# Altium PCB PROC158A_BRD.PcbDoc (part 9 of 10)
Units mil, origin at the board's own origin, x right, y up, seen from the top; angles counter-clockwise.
Board outline 3346.45 x 4921.26 mil, 8 copper layers (Top Layer, GND1, SIG1, PWR1, PWR2, SIG2, GND2, Bottom Layer), stack 54.534 mil thick; 718 components, 459 nets, 2307 pads, 1179 vias.
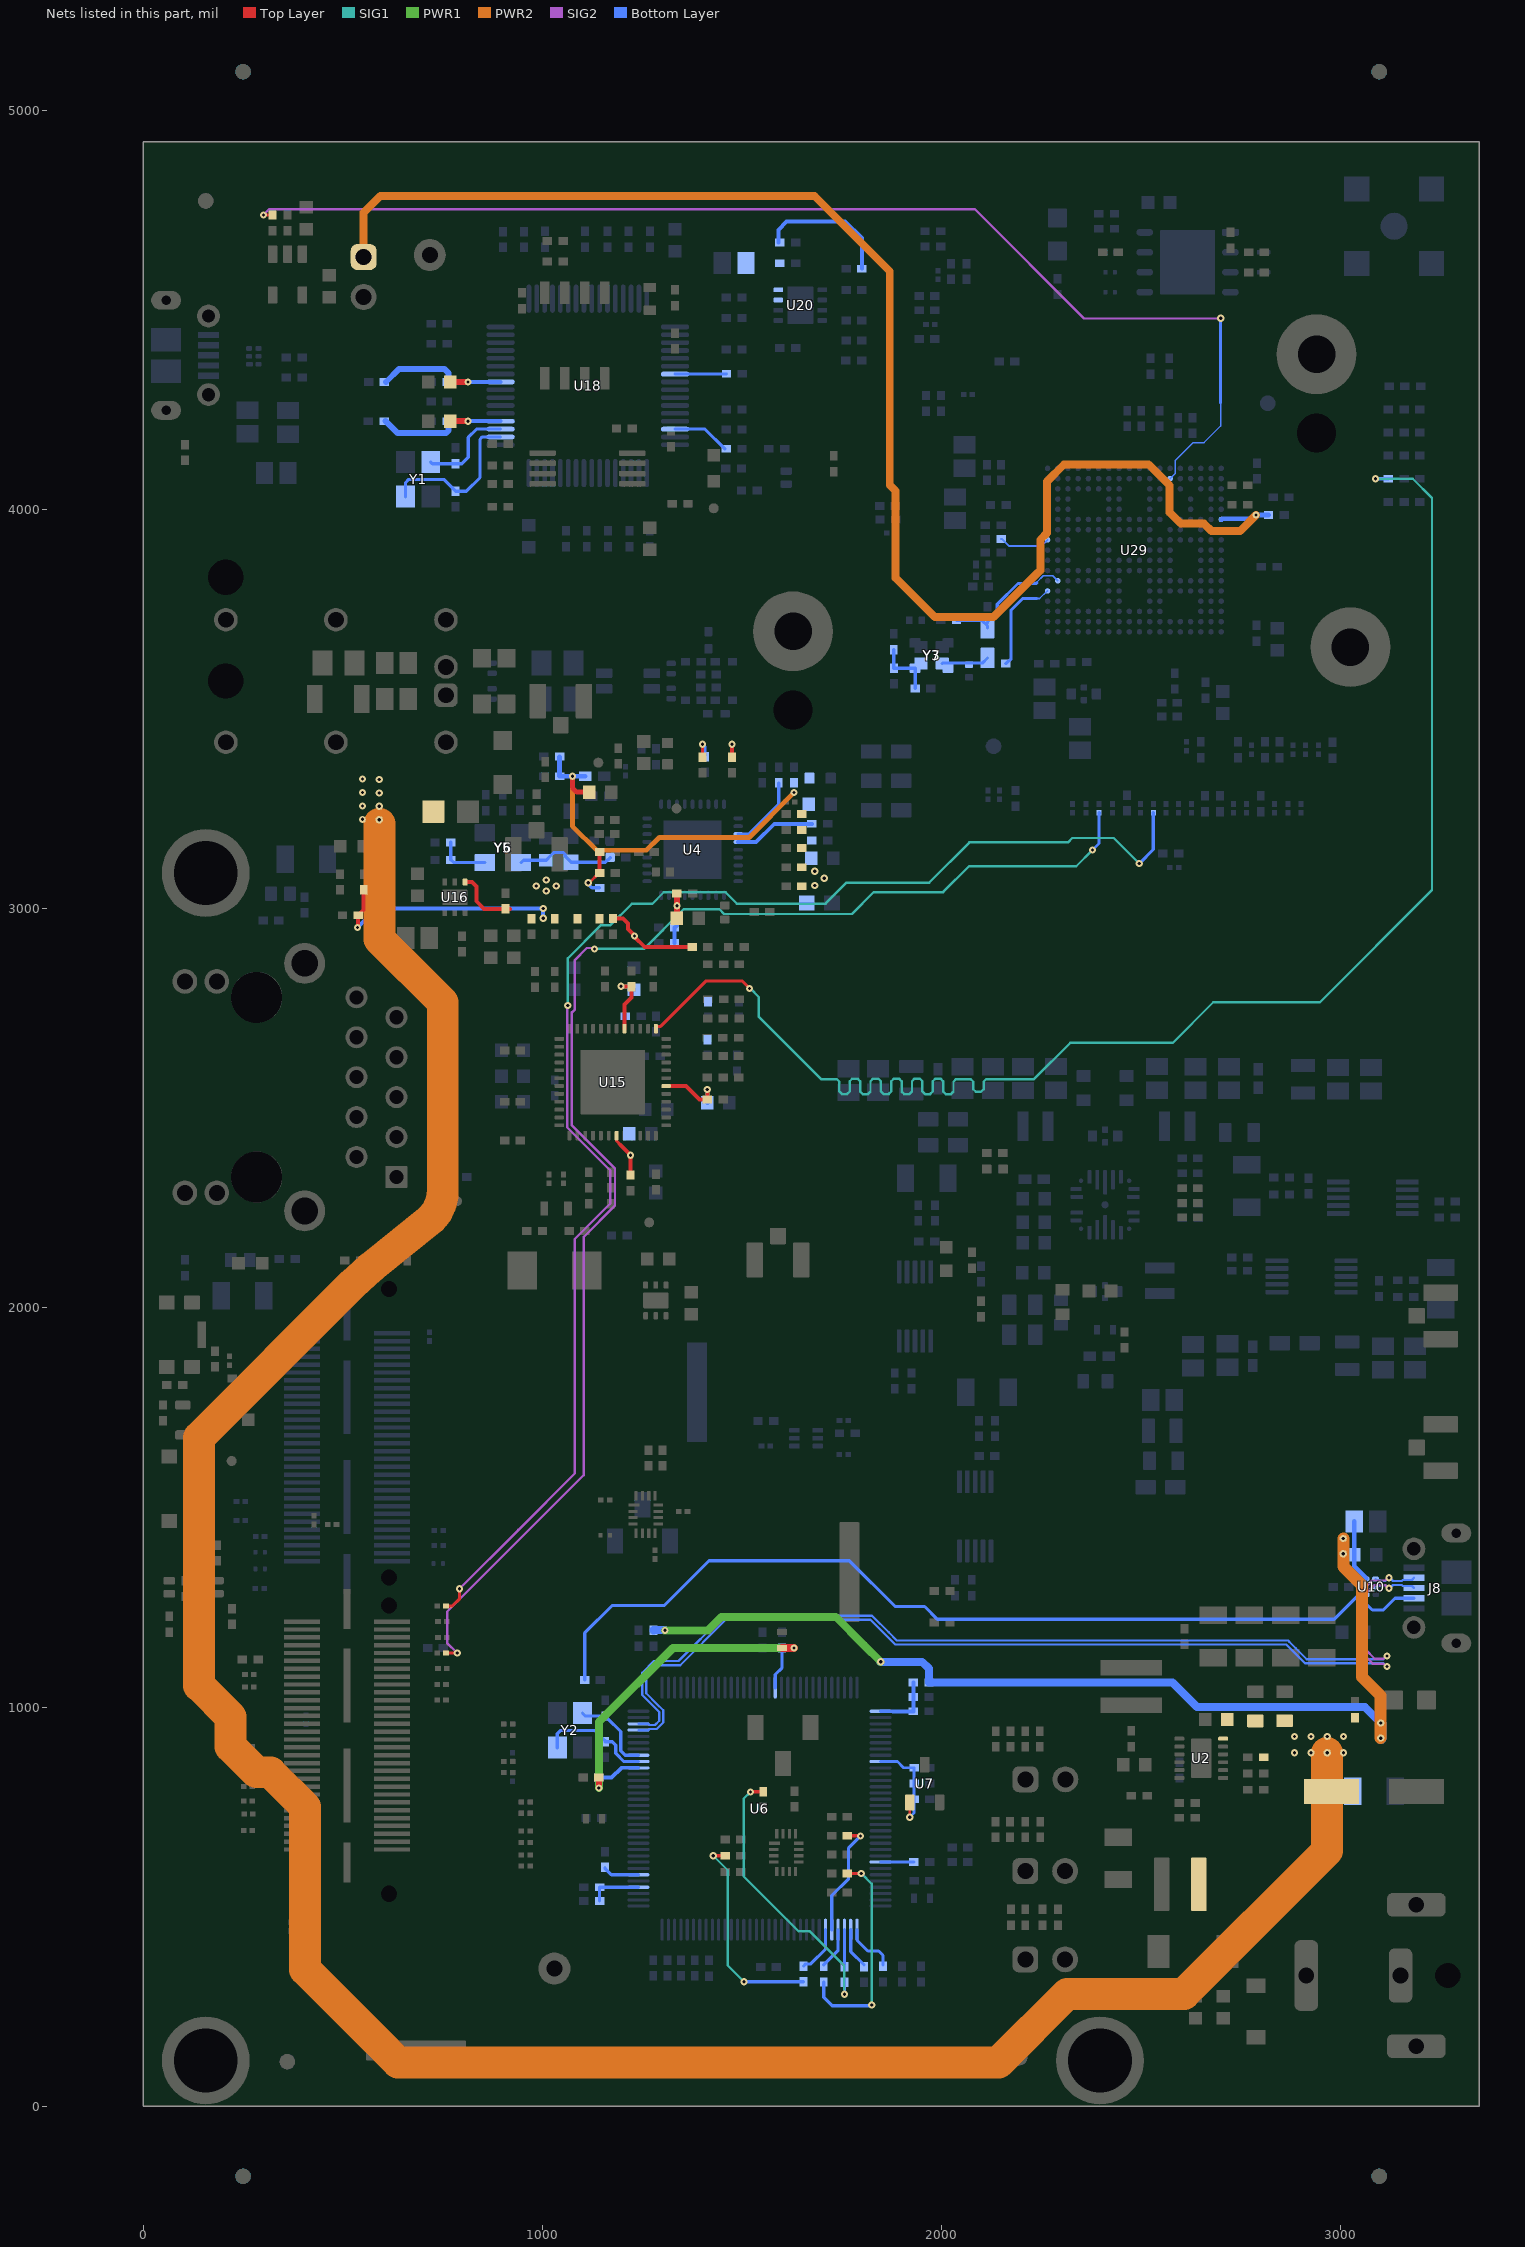
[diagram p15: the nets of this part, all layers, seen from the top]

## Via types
v1: diameter 18, hole 8, Top Layer to Bottom Layer, tented both sides, 1112 vias
v2: diameter 19.68, hole 7.87, Top Layer to Bottom Layer, 28 vias
v3: diameter 20, hole 10, Top Layer to Bottom Layer, tented both sides, 26 vias
v4: diameter 16/18/18/18/18/18/18/16 (per signal layer), hole 8, Top Layer to Bottom Layer, tented both sides, 13 vias

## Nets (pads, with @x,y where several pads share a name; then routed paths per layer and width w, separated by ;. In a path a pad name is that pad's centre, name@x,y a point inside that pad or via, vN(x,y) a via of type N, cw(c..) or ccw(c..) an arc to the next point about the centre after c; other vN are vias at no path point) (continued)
TX_CTRL: R101.2 U15.37 | length 3914.5
  Top Layer w8: U15.37@1284.77,2705.1 1295.97,2705.1 1410.08,2819.22 1499.78,2819.22 v1(1519,2800)
  SIG1 w6: v1(1519,2800) 1520.85,2800 1542,2778.85 1542,2773.48 1542.06,2773.42 1542.06,2728.92 1698.02,2572.95 1708.25,2572.95 1737.25,2572.95 1743.75,2566.45 1743.75,2542 1750.25,2535.5 1763.25,2535.5 1769.75,2542 1769.75,2567.88 1776.25,2574.38 1789.25,2574.38 1795.75,2567.88 1795.75,2542 1802.25,2535.5 1815.25,2535.5 1821.75,2542 1821.75,2567.88 1828.25,2574.38 1841.25,2574.38 1847.75,2567.88 1847.75,2542 1854.25,2535.5 1867.25,2535.5 1873.75,2542 1873.75,2567.88 1880.25,2574.38 1893.25,2574.38 1899.75,2567.88 1899.75,2542 1906.25,2535.5 1919.25,2535.5 1925.75,2542 1925.75,2567.88 1932.25,2574.38 1945.25,2574.38 1951.75,2567.88 1951.75,2542 1958.25,2535.5 1971.25,2535.5 1977.75,2542 1977.75,2567.88 1984.25,2574.38 1997.25,2574.38 2003.75,2567.88 2003.75,2542 2010.25,2535.5 2023.25,2535.5 2029.75,2542 2029.75,2566.45 2036.25,2572.95 2043.33,2572.95 2043.7,2572.95 2072.7,2572.95 2079.2,2566.45 2079.2,2547.8 2085.7,2541.3 2098.7,2541.3 2105.2,2547.8 2105.2,2566.45 2111.7,2572.95 2123.07,2572.95 2231.45,2572.95 2322.24,2663.74 2578.84,2663.74 2680.58,2765.48 2947.48,2765.48 3228.45,3046.45 3228.45,4028.55 3180.03,4076.97 v1(3087,4076.97)
  Bottom Layer w8: v1(3087,4076.97) R101.2@3119.26,4076.97
UART_TX_FTDI: R131.2 U18.39 | length 129.2
  Bottom Layer w8: U18.39@1332.18,4339.21 1332.55,4339.59 1460.69,4339.59 R131.2@1461.03,4339.25
V_GND: C172.2 R76.2 R79.2 Y5.4 Y6.4 | length 132.7
  Bottom Layer w8: R76.2@770.13,3166.22 R79.2@770.13,3121.72 772.1,3121.72 778.38,3115.44 Y5.4@855.78,3115.44
V_GND_50MHz: C178.2 R86.2 R87.2 Y3.4 Y7.4 | length 151.6
  Bottom Layer w8: R87.2@1879.89,3648.94 1879.89,3601.94 C178.2@1880.27,3602.32 1933.16,3602.32 Y7.4@1933.55,3602.71 ; R86.2@1933.67,3551.94 Y3.4@1933.67,3602.59
VBAT_INT: C99.1 C101.1 C118.2 C173.2 C195.1 L5.2 R7.1 R191.2 R331.2 U2.12 | length 6447.8
  PWR2 w80: 592.01,3212.8 592.01,2923.53 750.25,2765.29 750.25,2293.1 cw(c650.25,2293.1) 720.96,2222.39 571.45,2101.97 ccw(c615.41,2047.39) 568.51,2099.47 524.32,2059.68 140,1675.35 140,1054.38 219,975.38 219,901.22 283.46,836.75 318.21,836.75 405,749.97 405,343 638.59,109.41 2142.58,109.41 2314.68,281.5 2607.23,281.5 2965.84,640.11 v1(2965.84,885.39)
  other v1: 2884,885.39 2924.92,885.39 3006.76,885.39 2884,926.31 2924.92,926.31 2965.84,926.31 3006.76,926.31 591,3222.81 549,3223.81 591,3256.48 549,3257.48 591,3290.14 549,3291.14 591,3323.81 549,3324.81
VBGAP: C180.1 U29.K1 | length 129.9
  Bottom Layer w4.5: 2238.73,3908.81 2250.26,3908.81 2264.73,3923.28 U29.K1@2265.3,3923.84
  Bottom Layer w5: C180.1@2148.95,3926.41 2150.92,3926.41 2168.52,3908.81 2238.73,3908.81
VBUS_1_DETECT: C109.2 R284.1 R285.2 U6.1 | length 161.5
  Bottom Layer w8: U6.1@1846.93,989.49 1885.44,989.49
  Bottom Layer w10: 1878.33,989.49 R285.2@1928.95,989.49 C109.2@1928.95,1025.56 R284.1@1928.95,1061.91
VDD_1P0: C8.2 C11.2 C12.2 C13.2 C16.1 C20.1 FB2.2 R63.1 U4.21 | length 1139.3
  Top Layer w12: v1(1075.19,3331.81) 1075.19,3302.81 1086,3292 C11.2@1117,3292
  PWR2 w12: v1(1075.19,3331.81) 1075.19,3206.81 1135.75,3146.25 1260.44,3146.25 1292.5,3178.31 1517.5,3178.31 v1(1630,3290.81)
  Bottom Layer w8: U4.21@1490.4,3186.96 1517.06,3186.96 1592,3261.9 C20.1@1592,3315.13
  Bottom Layer w12: C12.2@1043,3380.81 C16.1@1043,3331.81 v1(1075.19,3331.81) R63.1@1107.38,3331.81
VDDC_1: C62.1 C64.2 C74.2 C75.2 U6.87 U6.115 | length 1055.2
  Top Layer w15: v1(1141.26,797.62) C74.2@1141.26,823.24
  Top Layer w20: C62.1@1600.04,1147.93 v1(1630,1147.93)
  PWR1 w20: v1(1141.26,797.62) 1141.26,962.26 1326.93,1147.93 v1(1630,1147.93)
  Bottom Layer w8: 1197.58,847.76 U6.87@1240.63,847.76 ; U6.115@1583.15,1048.54 1583.15,1081.5 1600.44,1098.79 C64.2@1600.44,1147.93 v1(1630,1147.93)
  Bottom Layer w10: v1(1141.26,797.62) C75.2@1141.26,823.24 ; C75.2@1143.21,823.24 1173.07,823.24 1197.58,847.76
VDDIO_ETH: C53.1 C158.1 C183.1 C184.1 C185.1 C186.1 R92.2 R108.2 R112.2 R132.2 R139.2 R141.2 R173.2 R211.2 R286.2 R295.1 R340.2 R342.2 U15.19 U15.30 U15.41 U16.4 | length 1471.7
  Top Layer w8: U15.19@1185.77,2431.68 1185.77,2418 1195.97,2407.8
  Top Layer w10: v1(537.01,2952.49) 537.7,2953.18 537.7,2982.91 R112.2@538.39,2983.6 552.17,2997.37 R108.2@552.17,3047.15 ; U16.4@806.17,3066.73 823.15,3066.73 834.77,3055.11 834.77,3018.63 854.06,2999.34 R295.1@907.18,2999.34 918.99,2999.34 ; R141.2@1177,2975.5 1201.84,2975.5 1214.12,2963.22 1214.12,2949.03 1230.42,2932.73 v1(1230.42,2931.38) 1230.42,2929.64 1256.24,2903.81 R211.2@1374.95,2903.81 ; 1195.97,2407.8 1220.92,2382.85 v1(1220.92,2382.45) ; v1(1196.68,2805.62) 1197.25,2805.04 1222.58,2805.04 C185.1@1223.16,2804.47 1223.16,2777.86 1205.44,2760.14 1205.44,2723.38 ; U15.41@1205.46,2699.4 1205.46,2723.37 ; C184.1@1220.92,2332.83 v1@1220.92,2378.09 ; U15.30@1309.79,2555.7 1359.88,2555.7 1393.53,2522.05 1413.27,2522.05 1413.31,2522.09 1413.31,2546.79 v1@1413.63,2547.1
  Bottom Layer w10: v1(537.01,2952.49) 584.81,3000.29 v1(1001.9,3000.29) 1001.95,3000.23 1001.95,2981.11 999,2978.16 v1@999,2976 ; v1(1196.68,2805.62) 1219.66,2805.62 C53.1@1228.92,2796.36 ; C186.1@1413.03,2513.53 v1(1413.03,2547.1)
  other v1: 1001.9,2976
VDDIO_ETH2: C32.2 C35.2 C36.2 C37.1 C44.1 C46.2 FB1.2 R13.2 R15.2 R16.2 R34.1 R46.1 R252.2 R253.2 R254.2 R255.2 R256.2 R257.2 R258.2 U4.22 U4.34 | length 603.8
  Top Layer w8: v1(1114.51,3064.96) 1116.36,3066.81 1119.05,3066.81 1141.23,3088.99 R46.1@1143.2,3088.99 ; R252.2@1401.29,3383.67 v1(1401.29,3412.15)
  Top Layer w10: R46.1@1143.2,3088.99 R13.2@1143.2,3142.2 ; R254.2@1474.75,3383.67 v1(1474.75,3412.15)
  Top Layer w15: C32.2@1336.83,2976.15 v1(1336.83,3007.39) R15.2@1336.83,3038.39
  Bottom Layer w8: v1(1114.51,3064.96) 1116.42,3063.04 1116.42,3059.6 1123.81,3052.21 R34.1@1143.2,3052.21 ; v1(1401.29,3412.15) 1407.02,3406.42 R253.2@1407.02,3383.59
  Bottom Layer w10: C46.2@1330.71,2914.18 C37.1@1330.71,2952.76 1331.99,2952.76 1336.83,2957.6 v1(1336.83,3007.39) U4.34@1336.83,3033.39 ; U4.22@1490.38,3167.25 1535.44,3167.25 1580.94,3212.75 C44.1@1674.81,3212.75
  other v1: 1009.58,3044.5 984.69,3056.5 1034.63,3056.5 1682,3057.81 1009.58,3071.56 1706,3076.33 1682,3093.55
VLDO_3V3: C93.1 C94.1 R182.1 R202.2 U20.3 U20.4 | length 343.4
  Bottom Layer w10: C94.1@1590.78,4668.86 1590.78,4700.64 1611.51,4721.37 1758.38,4721.37 1800.03,4679.72 R202.2@1800.03,4603.23
VPHY_FTDI: C68.1 C69.2 L3.2 U18.4 | length 366.6
  Top Layer w15: C68.1@772.94,4221.1 v1(813.55,4221.1)
  Bottom Layer w10: v1(813.55,4221.1) U18.4@895.17,4221.1
  Bottom Layer w15: L3.2@607.41,4221.1 637.27,4191.24 758.26,4191.24 765.07,4198.05 765.07,4221.1 v1(813.55,4221.1)
VPLL_FTDI: C72.1 C73.2 L4.2 U18.9 | length 371.7
  Top Layer w15: C72.1@769,4319.53 v1(813.55,4319.53)
  Bottom Layer w10: v1(813.55,4319.53) U18.9@895.17,4319.53
  Bottom Layer w15: L4.2@608.16,4319.53 641.1,4352.47 754,4352.47 765.07,4341.41 765.07,4319.53 v1(813.55,4319.53)
VPP_1P7: C150.2 P1.1 U29.M18 | length 3770.2
  PWR2 w20: P1.1@552.17,4632.33 552.17,4743.98 594,4785.81 1681,4785.81 1870,4596.81 1870,4061.55 1885,4046.55 1885,3828.39 1982.81,3730.57 2130.21,3730.57 2239.05,3839.42 2247.12,3847.49 2247.12,3924.12 2264,3941 2264,4070 2307.11,4113.11 2518.49,4113.11 2571,4060.6 2571,3993.02 2599.5,3964.52 2657.19,3964.52 2675.8,3945.91 2747.82,3945.91 v1(2787.81,3985.9)
  Bottom Layer w12: U29.M18@2700.34,3975.02 2700.81,3975.02 2702.46,3976.68 2777.78,3976.68 2787.01,3985.9 v1(2787.81,3985.9) ; v1@2788.12,3986.2 2816.59,3986.2 2816.89,3986.51 C150.2@2818.86,3986.51
VPP_EN: R159.1 U29.T13 | length 3010
  Top Layer w8: v1(301.31,4738.05) 301.48,4737.87 323.78,4737.87 R159.1@323.96,4737.7
  SIG2 w6: v1(301.31,4738.05) 315.2,4751.94 2083.37,4751.94 2356.9,4478.41 2698.58,4478.41 v1(2699.21,4479.03)
  Bottom Layer w4: U29.T13@2572.39,4077.38 2585.22,4090.21 2585.22,4122.59 2596.81,4134.18 2597.1,4134.47 2630.3,4167.67 2657.24,4167.67 2698.74,4209.17 2698.74,4267
  Bottom Layer w8: 2698.74,4267 2698.74,4478.57 v1(2699.21,4479.03)
WRMRST_FTDI: R330.1 U18.46 | length 144.7
  Bottom Layer w8: U18.46@1332.18,4201.42 1407.28,4201.42 R330.1@1456.51,4152.19
XDS_TCK: R353.1 R387.1 | length 696.9
  Top Layer w8: v1(1521.05,787.51) 1521.24,787.7 1553.03,787.7 R353.1@1553.23,787.9
  SIG1 w6: v1(1521.05,787.51) 1503.94,770.4 1503.94,576.06 1642.02,437.98 1669.94,437.98 1756.38,351.55 v1(1756.38,280.81)
  Bottom Layer w8: v1(1756.38,280.81) R387.1@1756.38,310.62
XDS_TDI: R355.1 R389.1 | length 526
  Top Layer w8: v1(1428,627.37) R355.1@1457.48,627.37
  SIG1 w6: v1(1428,627.37) 1464,591.37 1464,352.81 v1(1505,311.81)
  Bottom Layer w8: v1(1505,311.81) R389.1@1654.05,311.78
XDS_TDO: R359.1 U6.37 | length 297.3
  Top Layer w8: R359.1@1763.89,677.81 v1@1796.39,677.81
  Bottom Layer w8: U6.37@1724.88,442.24 1724.88,527.89 1767,570 1767,647.08 v1(1797.06,677.14)
XDS_TMS: R357.1 R388.1 | length 543.3
  Top Layer w8: R357.1@1763.89,582.99 1764.08,583.17 1798.63,583.17 v1(1798.82,583.36)
  SIG1 w6: v1(1798.82,583.36) 1825,557.17 v1(1825,253.81)
  Bottom Layer w8: R388.1@1704.82,311.19 1704.82,273.11 1725.95,251.97 1823.16,251.97 v1(1825,253.81)
XDSET_1_D_N: J8.2 U6.93 U10.1 | length 2592.4
  SIG2 w5.8: v1(3115.78,1101.9) 3113.28,1101.9 3106.28,1108.9 3079.99,1108.9 3051,1137.89 3051,1289.81 3078.03,1316.84 3111.5,1316.84 3118.5,1323.84 v1(3121,1323.84)
  Bottom Layer w5.65: U6.93@1240.63,942.24 1264.86,942.24 1267.63,945.02 1286.34,945.02 1302.52,961.19 1302.52,991.91 1287.21,1007.21 1260,1034.42 1260,1081.68 1283.36,1105.04 1345.04,1105.04 1458.5,1218.5 1821.5,1218.5 1883.52,1156.48 2863.52,1156.48 2910.2,1109.8 3106.29,1109.8 3114.19,1101.9 v1(3115.78,1101.9) ; U10.1@3086.64,1320.68 3089.03,1318.3 3096.67,1318.3 3099.03,1315.94 3111.52,1315.94 3119.42,1323.84 v1(3121,1323.84) 3122.59,1323.84 3130.49,1315.94 3152.67,1315.94 3155.32,1318.58 3178.02,1318.58 J8.2@3183.07,1323.63
XDSET_1_D_P: J8.3 U6.94 U10.2 | length 2551.6
  SIG2 w5.8: v1(3115.78,1127.9) 3113.28,1127.9 3106.28,1120.9 3084.96,1120.9 3063,1142.86 3063,1284.84 3083,1304.84 3111.5,1304.84 3118.5,1297.84 v1(3121,1297.84)
  Bottom Layer w5.65: U6.94@1240.63,957.99 1264.86,957.99 1267.63,955.22 1282.12,955.22 1292.32,965.42 1292.32,987.68 1276.71,1003.29 1249.8,1030.2 1249.8,1085.9 1279.14,1115.24 1340.82,1115.24 1454.27,1228.7 1825.73,1228.7 1828.72,1225.71 1867.21,1187.21 1887.74,1166.68 2867.74,1166.68 2870.73,1163.7 2887.21,1147.21 2914.42,1120 3106.29,1120 3114.19,1127.9 v1(3115.78,1127.9) ; U10.2@3087.63,1301 3090.01,1303.38 3096.67,1303.38 3099.03,1305.74 3111.52,1305.74 3119.42,1297.84 v1(3121,1297.84) 3122.59,1297.84 3130.49,1305.74 3152.67,1305.74 3155.32,1303.09 3178.02,1303.09 J8.3@3183.07,1298.04
XDSET_1_ID: J8.4 R152.1 U10.4 | length 2397.7
  Bottom Layer w8: R152.1@1105.81,1067.8 1105.81,1185.81 1174.55,1254.55 1305.45,1254.55 1417.28,1366.39 1769,1366.39 1883.39,1252 1957.3,1252 1989.3,1220 2983.21,1220 3044.52,1281.31 U10.4@3064.01,1281.31 3064.01,1258.07 3079,1243.08 3106.38,1243.08 3135.76,1272.45 J8.4@3183.07,1272.45
XDSET_1_VBUS: C45.1 R154.2 R161.2 R284.2 U10.6 | length 2698.9
  PWR1 w20: v1(1307.09,1192.2) 1414.6,1192.2 1448.41,1226.01 1734.74,1226.01 1805.74,1155 v1(1847.24,1113.5)
  PWR2 w30: v1@3006.13,1383.81 3006.13,1352.06 3052.49,1305.7 3052.49,1075.88 3099.82,1028.54 v1(3099.82,960.18) v1(3099.82,922.12) ; v1@3006.13,1384.08 v1@3006.13,1422.29
  Bottom Layer w12: C45.1@3033.4,1465.35 R161.2@3033.4,1381.17 3033.4,1352.51 U10.6@3063.63,1322.27
  Bottom Layer w20: R154.2@1278.34,1192.2 1278.34,1192.76 1278.5,1192.91 v1@1307.09,1192.91 ; v1(1847.24,1113.5) 1951.12,1113.5 1968.32,1096.31 R284.2@1968.32,1061.91 2578.09,1061.91 2640,1000 3060,1000 v1@3100,960 ; v1(3099.82,922.12) v1@3100,922.3
  Bottom Layer w30: v1@3100,922.3 v1@3100,960
  other v1: 3006.26,1383.94 3006.26,1422.42
XDSET_NRST: R155.1 U6.70 | length 93
  Bottom Layer w8: R155.1@1156.34,598.3 1156.34,596.34 1172.64,580.04 U6.70@1240.63,580.04
XDSET_OSC0: C70.1 U6.88 Y2.1 | length 287
  Bottom Layer w8: Y2.1@1037.27,898.25 1037.27,933.05 1045.68,941.46 1131.05,941.46 1151.46,921.05 1157.31,915.21 C70.1@1157.31,913.24 1174.88,913.24 1183.4,904.72 1183.4,884.34 1204.23,863.5 U6.88@1240.63,863.5
XDSET_OSC1: C63.2 U6.89 Y2.3 | length 213.4
  Bottom Layer w8: Y2.3@1100.27,984.86 1107.45,977.68 C63.2@1157.31,977.68 1157.31,975.71 1163.15,969.87 1165.12,969.87 1196.3,938.68 1196.3,890.63 1207.62,879.32 1240.57,879.32 U6.89@1240.63,879.25
XDSET_TCK: R387.2 U6.35 | length 92.3
  Bottom Layer w8: R387.2@1756.38,349.99 U6.35@1756.38,442.24
XDSET_TDI: R389.2 U6.38 | length 121.5
  Bottom Layer w8: R389.2@1654.05,351.15 1659.5,356.59 1672.44,356.59 1709.14,393.29 U6.38@1709.14,442.24
XDSET_TMS: R388.2 U6.36 | length 102.6
  Bottom Layer w8: R388.2@1704.82,354.5 1740.63,390.31 U6.36@1740.63,442.24
XDSET_UARTA_RX: R129.2 U6.34 | length 102.2
  Bottom Layer w8: U6.34@1772.13,442.24 1772.13,387.55 R129.2@1805.76,353.93
XDSET_UARTA_TX: R128.2 U6.33 | length 130.5
  Bottom Layer w8: U6.33@1787.88,442.24 1787.88,416.34 1815.23,388.99 1842.07,388.99 1853.15,377.91 R128.2@1853.15,354.5
XDSET_UARTB_TX: R136.2 U6.25 | length 83.4
  Bottom Layer w8: U6.25@1846.93,611.54 R136.2@1930.31,611.54
XDSET_VBAT: C49.1 R134.1 U6.68 | length 132
  Bottom Layer w8: R134.1@1143.21,513.97 C49.1@1143.21,548.54 U6.68@1240.63,548.54
XDSET_VREFA: C66.2 C67.2 R140.1 U6.9 U7.1 | length 256.1
  Top Layer w7: v1(1920.03,724) U7.1@1920.03,761.14
  Bottom Layer w7: U6.9@1846.93,863.5 1888.99,863.5 1904.39,848.1 C66.2@1930.89,848.1 C67.2@1930.89,808.77 R140.1@1930.89,769.02 1930.89,734.86 v1(1920.03,724)
XI_FTDI: C84.1 U18.2 Y1.1 | length 401.2
  Bottom Layer w8: Y1.1@657.29,4032.13 657.29,4067.56 665.17,4075.44 752.83,4075.44 C84.1@782.36,4045.91 809.61,4045.91 843.6,4079.9 843.6,4175.65 849.68,4181.73 U18.2@895.17,4181.73
XO_50MHz: C108.1 R85.2 R189.1 Y3.3 Y7.3 | length 119.1
  Bottom Layer w8: Y3.3@2001.46,3614.27 2002.33,3615.13 2068.85,3615.13 2101.88,3615.13 R189.1@2114.86,3628.11
XO_combined: C95.1 R186.2 R246.1 R248.2 Y5.3 Y6.3 | length 251.7
  Bottom Layer w8: Y5.3@946.33,3115.44 952.46,3121.57 R248.2@1008.66,3121.57 1009.65,3121.57 1021.25,3133.17 1028.54,3140.47 1052.61,3140.47 1057.3,3135.79 1057.3,3131.01 C95.1@1072,3116.31 1157.33,3116.31 1162.34,3121.32 1163.16,3121.32 1169.68,3127.83 R246.1@1169.68,3128.27
XO_FTDI: C83.1 U18.3 Y1.3 | length 241.6
  Bottom Layer w8: Y1.3@720.28,4118.74 724.22,4114.81 C83.1@782.36,4114.81 798.14,4114.81 814.15,4130.81 814.15,4180.68 834.89,4201.42 U18.3@895.17,4201.42
XREF_CLK0: R25.2 R84.1 | length 3595.8
  Top Layer w8: R84.1@758.27,1253.41 774.77,1253.41 792.32,1270.96 v1(792.32,1296.56)
  SIG1 w6: v1(1063.22,2757.49) 1063.22,2875.39 1146.64,2958.81 1170.39,2958.81 1223.49,3011.92 1274.92,3011.92 1304,3041 1458.72,3041 1486.91,3012.81 1709.19,3012.81 1761.81,3065.43 1968.8,3065.43 2069.37,3166 2316.12,3166 2327.12,3177 2431,3177 v1(2495,3113)
  SIG2 w6: v1(792.32,1296.56) 939.67,1443.91 1080.84,1585.08 1080.84,2172.26 1169.86,2261.29 1169.86,2344.29 1061.85,2452.3 1061.85,2756.12 v1(1063.22,2757.49)
  Bottom Layer w8: v1(2495,3113) 2530.2,3148.2 R25.2@2530.2,3240.22
XREF_CLK1: R21.2 R90.1 | length 3517.8
  Top Layer w8: R90.1@760.24,1135.3 v1(786.39,1135.3)
  SIG1 w6: v1(1130.72,2899.25) 1254.15,2899.25 1353.9,2999 1442.77,2999 1455.05,2986.73 1775.29,2986.73 1830,3041.43 2003.54,3041.43 2068.48,3106.37 2337.37,3106.37 v1(2378,3147)
  SIG2 w6: v1(786.39,1135.3) 761.22,1160.48 761.22,1238.79 1103.35,1580.92 1103.35,2177.8 1181.86,2256.32 1181.86,2349.26 1073.85,2457.27 1073.85,2740.18 1081.22,2747.55 1081.22,2871.57 1111.03,2901.39 1128.58,2901.39 v1(1130.72,2899.25)
  Bottom Layer w8: v1(2378,3147) 2394.31,3163.31 2394.31,3237.14 2394.61,3237.44 R21.2@2394.61,3240.22
XTALM: R85.1 U29.E1 | length 251.7
  Bottom Layer w4: 2238.73,3777.06 2245.42,3777.06 2264.25,3795.89 U29.E1@2265.3,3795.89
  Bottom Layer w5.05: 2238.5,3777.06 2238.73,3777.06
  Bottom Layer w8: R85.1@2160.23,3614.51 2162.19,3614.51 2173.96,3626.27 2173.96,3748.32 2202.7,3777.05 2238.49,3777.05
XTALP: R83.1 R189.2 R269.1 U29.F2 | length 337.3
  Bottom Layer w4: 2238.73,3816.18 2238.73,3818.6 2254.37,3834.25 2270.98,3834.25 2278.12,3834.25 U29.F2@2290.89,3821.48
  Bottom Layer w8: R83.1@2037.23,3722.51 2100.75,3722.51 2114.86,3708.4 R189.2@2114.86,3702.91 ; R269.1@2114.86,3716.51 2114.86,3718.48 2120.7,3724.32 2127.79,3724.32 2139.16,3735.69 2139.16,3762.45 2191.39,3814.68 2237.23,3814.68 2238.73,3816.18
pads on no net: D15.1S D15.2S D17.1S D17.2S D18.1S D18.2S D19.1S D19.2S FID1.1 FID2.1 FID3.1 FID4.1 FID5.1 FID6.1 FID7.1 FID8.1 FID9.1 FID10.1 FID11.1 FID12.1 FID13.1 FID14.1 FID15.1 FID16.1 J4.ALIGN1 J4.ALIGN2 J7.1 J7.2 J7.3 J7.23 J7.25 J7.31 J7.35 J7.47 J7.MH1 J7.MH2 J8.7 J8.8 J9. J12.ALIGN J19.10 J19.11 J19.14 J19.18 J19.20 J19.22 J19.24 J19.26 J19.28 J19.30 J19.32 J19.34 J19.35 J19.36 J19.37 J19.38 J19.39 J19.40 J19.41 J19.43 J19.44 J19.45 J19.46 J19.47 J19.49 J19.50 J19.51 J19.52 J19.53 J19.55 J19.56 J19.59 J19.MH1 J19.MH2 LBL1.0 SW1.1 SW1.3 SW2.1 SW2.3 U2.11 U4.17 U4.20 U6.2 U6.3 U6.4 U6.5 U6.6 U6.11 U6.12 U6.13 U6.14 U6.15 U6.18 U6.19 U6.20 U6.21 U6.22 U6.23 U6.24 U6.27 U6.29 U6.30 U6.31 U6.32 U6.41 U6.42 U6.43 U6.44 U6.45 U6.46 U6.49 U6.50 U6.53 U6.54 U6.56 U6.57 U6.65 U6.67 U6.71 U6.72 U6.73 U6.74 U6.75 U6.76 U6.77 U6.78 U6.81 U6.82 U6.83 U6.84 U6.85 U6.86 U6.91 U6.92 U6.97 U6.98 U6.99 U6.100 U6.102 U6.103 U6.104 U6.105 U6.106 U6.107 U6.108 U6.109 U6.110 U6.111 U6.112 U6.116 U6.117 U6.118 U6.119 U6.120 U6.121 U6.123 U6.124 U6.125 U6.126 U6.127 U6.128 U7.3 U9.3 U11.3 U12.3 U13.3@725.63,2668.11 U13.8@758.51,2668.11 U14.3@725.63,2462.03 U14.8@758.51,2462.03 U15.13 U15.20 U15.21 U15.22 U15.23 U15.48 U15.49@1121.99,2511.61 U15.49@1121.99,2565.54 U15.49@1121.99,2619.48 U15.49@1175.93,2511.61 U15.49@1175.93,2565.54 U15.49@1175.93,2619.48 U15.49@1229.87,2511.61 U15.49@1229.87,2565.54 U15.49@1229.87,2619.48 U16.5 U16.7@762.86,3028.35 U16.7@798.3,3028.35 U17.2 U17.5 U17.7@1266.22,2018.66 U17.7@1301.66,2018.66 U18.21 U18.22 U18.23 U18.24 U18.29 U18.30 U18.33 U18.38 U18.40 U18.41 U18.43 U18.44 U18.57 U18.58 U18.59 U18.60 U19.6 U19.7 U20.7 U20.9@1645.9,4487.01 U20.9@1645.9,4536.61 U22.3 U27.4

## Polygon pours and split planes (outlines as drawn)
GND on Top Layer "Top Layer-GND" (solid, remove dead copper, pour order 771): 3346.45,4921.26 3346.45,0 0,0 0,4921.26
REGOUT_3V3 on Top Layer "REGOUT_3V3_L01_P682" (solid, remove dead copper, pour order 682): 2986.45,1251.5 2978.62,1259.33 2978.62,1293.66 2986.45,1301.15 2986.45,1371.36 2945.81,1412 2532,1412 2398.23,1278.23 2398.23,1076.32 2551.77,1076.32 2551.77,1151.77 2584.57,1184.57 2622.18,1184.57 2645.8,1208.19 2986.45,1208.19
REGOUT_3V3 on Top Layer "REGOUT_3V3_L01_P632" (solid, remove dead copper, pour order 632): 2106.58,2005 2058.09,2005 2052.33,2010.76 2052.33,2048.33 2059,2055 2094,2055 2108.84,2040.16 2108.84,2005
VBAT_INT on Top Layer "VBAT_INT_L01_P703" (solid, remove dead copper, pour order 703): 753.22,3214.57 754.46,3215.81 754.46,3281.54 691.04,3344.96 554.96,3344.96 539,3329 539,3220 544.43,3214.57
NetD16_1 on Top Layer "NETD16_1_L01_P633" (solid, remove dead copper, pour order 633): 787.08,3214.68 785.95,3215.81 785.95,3270.24 787.08,3271.37 860.54,3271.37 876.89,3287.72 876.89,3334.96 924.13,3334.96 924.13,3261.3 877.51,3214.68
3V3 on Top Layer "3V3_L01_P643" (solid, remove dead copper, pour order 643): 2553.37,3565.1 ccw(c2553.37,3629.45) 2598.88,3583.95 2618.71,3603.79 cw(c2636.37,3586.13) 2636.37,3611.1 2627.37,3620.1 ccw(c2617.47,3610.2) 2617.47,3624.2 ccw(c2609.99,3616.72) 2609.99,3627.3 2578.87,3627.3 ccw(c2578.87,3586.5) 2550.02,3615.35 2537.4,3602.72 ccw(c2552.42,3587.7) 2531.17,3587.7 2531.17,3580.77 ccw(c2546.54,3580.77) 2535.67,3569.9 ccw(c2547.26,3581.49) 2547.26,3565.1 2553.27,3565.1
1V2 on Top Layer "1V2_L01_P659" (solid, remove dead copper, pour order 659): 2739.13,4002.16 2739.13,4070.71 2736.84,4073 2614.67,4073 2607.51,4065.83 2607.51,4003 2630.57,3979.93 2650.17,3979.93 2653.73,3983.49 2653.73,4050.79 2659.08,4056.14 2672.86,4056.14 2703.66,4025.34 2703.66,4002.16
VDDIO_ETH on Top Layer "Top Layer-VDDIO_ETH" (solid, remove dead copper, pour order 734): 1210.1,3011.15 1210.1,2965.79 897.34,2965.79 897.34,3011.16
NetC21_2 on Top Layer "NETC21_2_L01_P648" (solid, remove dead copper, pour order 648): 2398.23,1024.22 2398.23,985.64 2455.26,928.61 2485.39,928.61 2498.19,915.81 2606.69,915.81 2607.84,916.97 2607.84,968.15 2551.77,1024.22
REGOUT_3V3 on Top Layer "REGOUT_3V3_L01_P652" (solid, remove dead copper, pour order 652): 1652.02,917.76 1652.02,980.75 1688.27,1017 1705,1017 1712,1010 1712,938.37 1691.39,917.76
3V3_VIO on Top Layer "3V3_VIO_L01_P672" (solid, remove dead copper, pour order 672): 2713.64,4666.77 2713.64,4618.36 2747.82,4584.19 2780.7,4584.19 2780.7,4672.3 2775,4678 2758,4678 2746.77,4666.77
AGND on Top Layer "AGND_L01_P675" (solid, remove dead copper, pour order 675): 21 vertices, not listed, extent 2346.48,2223.31 2472.48,2293.31
PVIN3V3 on Top Layer "PVIN3V3_L01_P677" (solid, remove dead copper, pour order 677): 2396,1599 2396,1560 2405,1551 2470,1551 2499,1580 2499,1840 2499,1880.84 2467.84,1912 2436.03,1912 2396,1871.97 2396,1842
PMIC_LDO_1V0 on Top Layer "PMIC_LDO_1V0_L01_P679" (solid, remove dead copper, pour order 679): 2392.72,2092.28 2380.91,2080.47 2380.91,2025.72 2379.78,2024.59 2288.39,2024.59 2286.42,2026.56 2286.42,2077.04 2348.91,2139.53 2383.86,2139.53 2392.72,2130.67
PVIN3V3 on Top Layer "PVIN3V3_L01_P687" (solid, remove dead copper, pour order 687): 2483.69,2493.82 2473.51,2504 2334,2504 2320,2490 2320,2450 2333.19,2436.81 2476.1,2436.81 2483.69,2444.4
VDDIO_ETH2 on Top Layer "Top Layer-VDDIO_ETH2" (solid, pour order 765): 1025.71,3092.02 1053.4,3064.33 1053.4,3061.55 1053.4,3031.08 1053.81,3030.67 1004.5,3030.67 987.33,3030.67 971,3047 971,3065 998.02,3092.02
ERTH_GND on Top Layer "ERTH_GND_L01_P716" (solid, remove dead copper, pour order 716): 362.83,2133.63 482.54,2253.34 482.54,2818.61 523.85,2859.92 523.85,3099.49 374.2,3099.48 181.29,2906.57 0,2906.57 0,2214.38 144.93,2214.38 225.68,2133.63
VBAT_INT on Top Layer "VBAT_INT_L01_P702" (solid, remove dead copper, pour order 702): 19 vertices, not listed, extent 2615,481.81 3045.54,985.45
NetC104_1 on Top Layer "Top Layer-NetC104_1" (solid, remove dead copper, pour order 722): 2599.66,439.47 2624.98,464.8 2928.02,464.8 2947.34,445.48 2947.34,239.12 2841.68,239.12 2828.7,252.09 2624.02,252.09 2599.66,276.45
NetC100_1 on Top Layer "Top Layer-NetC100_1" (solid, remove dead copper, pour order 726): 2576.21,349.16 2576.21,622.74 2405,622.74 2405,349.16
REGOUT_3V3 on Top Layer "Top Layer-REGOUT_3V3 1" (solid, remove dead copper, pour order 747): 681.13,3060.82 670.29,3071.65 670.29,3140.81 700,3140.81 703.76,3137.06 703.76,3090.06 713,3080.81 759,3080.81 764.83,3074.98 764.83,3057.18 710.63,3057.18 706.99,3060.82
VDDIO_ETH2 on Top Layer "VDDIO_ETH2_L01_P709" (solid, remove dead copper, pour order 709): 1708.17,3044 1718.85,3054.68 1718.85,3081.63 1696,3104.48 1696,3143.62 1696,3237.06 1684.23,3248.83 1637.94,3248.83 1637.94,3046.26 1637.89,3046.21 1640.11,3044
2V5_ETH on Top Layer "Top Layer-2V5_ETH" (solid, remove dead copper, pour order 735): 763.1,2998.19 763.1,2863.36 693.44,2863.36 693.44,2953.71 737.93,2998.19
NetC149_2 on Top Layer "Top Layer-NetC144_1" (solid, remove dead copper, pour order 737): 513.96,4556.1 528.55,4570.69 590.17,4570.69 590.17,4506.02 560.91,4476.76 373.17,4476.76 373.17,4556.1
1V0_ETH on Top Layer "Top Layer-1V0_ETH" (solid, remove dead copper, pour order 740): 1296.98,2141.21 1311.38,2155.61 1386.85,2155.61 1395.36,2164.13 1395.36,2183.88 1459.39,2183.88 1459.39,2075.16 1356.85,2075.16 1329.08,2047.39 1302.53,2047.39 1302.53,2092.99 1296.98,2098.54
NetJ10_6 on Top Layer "Top Layer-NetJ10_6" (solid, remove dead copper, pour order 743): 192.3,4450.41 199.96,4458.07 199.96,4517.55 164.33,4553.18 -19.57,4553.18 -19.57,4151.18 192.3,4151.18 192.3,4304.73 179.15,4317.88 113.86,4317.88 104.25,4327.49 104.25,4449.7
GND on GND2 "GND1-GND" (solid, remove dead copper, pour order 755): 0,4921.25 3346.45,4921.25 3346.45,0 0,0
AGND on GND2 "AGND_L07_P655" (solid, remove dead copper, pour order 655): 21 vertices, not listed, extent 2346.48,2223.31 2472.48,2293.31
ERTH_GND on GND2 "ERTH_GND_L07_P662" (solid, remove dead copper, pour order 662): 362.83,2133.24 482.54,2252.95 482.54,2818.22 523.85,2859.53 523.85,3099.1 374.2,3099.09 181.29,2906.18 0,2906.18 0,2213.99 144.93,2213.99 225.68,2133.24
GND on SIG1 "GND_L03_P727" (solid, remove dead copper, pour order 727): 0,4921.25 0,0 3346.45,0 3346.45,4921.26
AGND on SIG1 "AGND_L03_P650" (solid, remove dead copper, pour order 650): 21 vertices, not listed, extent 2346.48,2223.31 2472.48,2293.31
FTDI_VBUS on SIG1 "SIG1-FTDI_VBUS" (solid, remove dead copper, pour order 688): 1555.33,4445.07 1555.33,4340.6 1565.72,4330.22 1604,4330.22 1623.26,4349.26 1623.26,4385.07 1664.19,4426 1805,4426 1814,4435 1814,4449 1806,4457 1567.26,4457
FTDI_VBUS on SIG1 "SIG1-FTDI_VBUS 1" (solid, remove dead copper, pour order 657): 354.26,4086.01 343.71,4096.56 343.71,4151.46 354.15,4161.9 395.51,4161.9 447.3,4161.9 457.04,4152.45 457.04,4096.49 446.54,4086.01 410,4086.01
GND on SIG2 "GND_L06_P725" (solid, remove dead copper, pour order 725): 0,4921.25 0,0 3346.45,0 3346.45,4921.25
AGND on SIG2 "AGND_L06_P689" (solid, remove dead copper, pour order 689): 21 vertices, not listed, extent 2346.48,2223.31 2472.48,2293.31
GND on Bottom Layer "C" (solid, remove dead copper, pour order 767): 0,4921.26 3346.45,4921.26 3346.45,0.01 0,0.01
AGND on Bottom Layer "AGND_L08_P769" (solid, remove dead copper, pour order 769): 2187.58,2289.89 2187.58,2197.61 2219.08,2197.61 2219.08,2229.08 2227,2237 2227,2250 2218.76,2258.24 2218.76,2290.2 2187.27,2290.2
SW_B2 on Bottom Layer "SW_B2_L08_P768" (solid, remove dead copper, pour order 768): 2280.06,2492.4 2376.17,2396.29 2374.92,2362.92 2375.03,2362.81 2375.03,2296.11 2373.06,2294.14 2366.34,2294.14 2365.19,2295.29 2365.19,2342.07 2358.06,2349.17 2315.96,2349.07 2252.5,2412.54 2252.5,2492.4
1V0 on Bottom Layer "1V0_L08_P671" (solid, remove dead copper, pour order 671): 2405,3626 2353,3678 2353,3697 2349.65,3700.35 2313.07,3700.35 2295,3682.28 2295,3441 2302.65,3433.35 2403.35,3433.35 2405,3435
1V8 on Bottom Layer "1V8_L08_P660" (solid, remove dead copper, pour order 660): 18 vertices, not listed, extent 2204,3524 2297,3696
REGOUT_3V3 on Bottom Layer "REGOUT_3V3_L08_P642" (solid, remove dead copper, pour order 642): 2910.94,1261 2919.36,1269.42 2919.36,1399.64 2901,1418 2744,1418 2683,1479 2683,1636 2673.4,1645.61 2570.2,1645.61 2560.04,1635.45 2560.04,1364.96 2664,1261
SW_B1 on Bottom Layer "SW_B1_L08_P700" (solid, remove dead copper, pour order 700): 2573,2418.28 2520.68,2365.96 2460.9,2366.1 2453.77,2359 2453.77,2312.22 2452.62,2311.07 2445.9,2311.07 2443.93,2313.04 2443.93,2391.33 2545,2492.4 2573,2492.4
PVIN3V3 on Bottom Layer "PVIN3V3_L08_P698" (solid, remove dead copper, pour order 698): 20 vertices, not listed, extent 2258.33,2296.7 2567.56,2567.13
1V0_ETH on Bottom Layer "PWR2-1V0_ETH" (solid, pour order 758): 26 vertices, not listed, extent 936.38,2080.95 1527.56,2814.98
VDDIO_ETH on Bottom Layer "PWR1-VDDIO_ETH" (solid, remove dead copper, pour order 719): 1166,2793.28 1166,2415.45 1208.98,2372.47 1252.98,2372.47 1252.98,2660.05 1380.61,2660.05 1380.61,2499.37 1450.74,2499.37 1450.75,2782.81 1217.2,3016.36 984.96,3016.36 984.96,2934.86 1024.42,2934.86
PMICOUT_1V0 on Bottom Layer "PMICOUT_1V0_L08_P701" (solid, remove dead copper, pour order 701): 19 vertices, not listed, extent 1979.06,2377.97 2231.06,2566.5
1V2 on Bottom Layer "1V2_L08_P673" (solid, remove dead copper, pour order 673): 2561.66,4054.75 2573.77,4066.86 2616.28,4066.86 2636.56,4046.57 2636.56,4043.37 2643,4036.93 2652.12,4036.93 2653.81,4035.24 2653.81,4000.54 2663.26,3991.08 2663.26,3975.73 2645.33,3957.8 2591.21,3957.8 2561.66,3987.34
1V2 on Bottom Layer "1V2_L08_P691" (solid, remove dead copper, pour order 691): 3215.54,2079.73 3215.54,2123.03 3211.76,2126.81 3094,2126.81 3088,2132.81 3088,2186.81 3098,2196.81 3287,2196.81 3302,2181.81 3302,2097.29 3284.43,2079.73
NERR_MCU on Bottom Layer "NERR_MCU_L08_P634" (solid, remove dead copper, pour order 634): 2315.96,2342.88 2322.16,2349.07 2350.05,2349.07 2355.35,2343.77 2355.35,2313.6 2354.19,2312.45 2324.02,2312.45 2315.96,2320.51
NetR52_2 on Bottom Layer "NETR52_2_L08_P635" (solid, remove dead copper, pour order 635): 2464.77,2312.45 2497.26,2312.45 2500.33,2315.51 2500.33,2344.36 2496.38,2348.31 2468.15,2348.31 2463.62,2343.78 2463.62,2313.6
1V2 on Bottom Layer "1V2_L08_P670" (solid, remove dead copper, pour order 670): 2675.81,3555.19 2687.27,3543.73 2687.27,3528.25 2720.73,3528.25 2720.73,3566.27 2628,3659 2618,3659 2618,3641 2651,3608 2651,3555.19
1V0 on Bottom Layer "1V0_L08_P637" (solid, remove dead copper, pour order 637): 20 vertices, not listed, extent 1937,3968.16 2265.3,4058
1V2 on Bottom Layer "1V2_L08_P666" (solid, remove dead copper, pour order 666): 18 vertices, not listed, extent 2689.99,3668 2887,3778.73
3V3 on Bottom Layer "3V3_L08_P645" (solid, remove dead copper, pour order 645): 2736.45,4009.55 2751.55,4009.55 2782.52,4040.52 2843,4040.52 2843,4020 2785,4020 2759,3994 2734.12,3994 2727.51,4000.61
1V2 on Bottom Layer "1V2_L08_P658" (solid, remove dead copper, pour order 658): 2655.7,4178.7 2628.47,4178.7 2628.47,4178.47 2585,4135 2582.97,4137.03 2582.97,4210.32 2649.32,4210.32 2658,4219 2658,4261 2662,4265 2676,4265 2680,4261 2680,4203
1V8 on Bottom Layer "1V8_L08_P638" (solid, remove dead copper, pour order 638): 1990.02,4075.28 2081,4075.28 2081,4124.81 2023.5,4124.81 2016.03,4132.28 1973.08,4132.28 1961.68,4120.88 1961.68,4103.62
PVIN_LDO_LS1 on Bottom Layer "PVIN_LDO_LS1_L08_P704" (solid, remove dead copper, pour order 704): 18 vertices, not listed, extent 2151.25,1982.19 2375,2166
3V3_VIO on Bottom Layer "3V3_VIO_L08_P639" (solid, remove dead copper, pour order 639): 2405.44,4713.17 2363.17,4713.17 2348,4698 2348,4666 2353,4661 2401,4661 2405.44,4665.44
2V5_ETH on Bottom Layer "PWR2-2V5_ETH" (solid, pour order 720): 834.89,2681.38 931.63,2681.38 931.63,2628.93 1017.9,2628.93 1017.9,2688.6 801.1,2905.4 692.55,2905.4 692.55,2873.55 728.68,2837.42 728.68,2437.76 1005.4,2437.76 1005.4,2530.69 931.38,2530.69 931.38,2491.6 834.89,2491.6
XDSET_1_VBUS on Bottom Layer "XDSET_1_VBUS_L08_P694" (solid, remove dead copper, pour order 694): 3054.45,1437.79 3049.15,1432.48 3049.15,1364.44 3001.09,1364.44 2982.45,1383.08 2982.45,1474.08 3001.28,1492.91 3055.05,1492.91 3055.05,1437.79
+3.3VD on Bottom Layer "+3.3VD_L08_P640" (solid, remove dead copper, pour order 640): 2089.16,2005 2124,2005 2124,2077.19 2089.16,2077.19
SYNC_CLK on Bottom Layer "SYNC_CLK_L08_P681" (solid, remove dead copper, pour order 681): 2241.81,2071.27 2273.31,2071.27 2355.35,2153.31 2355.35,2203.03 2354.19,2204.18 2324.44,2204.18 2324.02,2204.18 2322.87,2203.03 2322.87,2152.32 2275.28,2104.74 2241.81,2104.74
PVIN3V3 on Bottom Layer "PVIN3V3_L08_P641" (solid, remove dead copper, pour order 641): 2242.7,2180.15 2279.15,2180.15 2294,2195 2308,2195 2311,2192 2311,2170 2287.69,2146.69 2242.7,2146.69
PVIN3V3 on Bottom Layer "PVIN3V3_L08_P669" (solid, remove dead copper, pour order 669): 2117.24,2300.95 2111.19,2307 2111.19,2325.5 2115.65,2329.97 2173.49,2329.97 2177.15,2333.62 2224.5,2333.62 2224.5,2310 2193.01,2310 2183.95,2300.95
VDD_1P0 on Bottom Layer "VDD_1P0_L08_P718" (solid, remove dead copper, pour order 718): 1582.16,3326.94 1572.73,3317.51 1572.73,3245.08 1682.75,3245.08 1682.75,3338.51 1680.67,3340.59 1653.78,3340.59 1640.13,3326.94
VPP_1P7 on Bottom Layer "VPP_1P7_L08_P644" (solid, remove dead copper, pour order 644): 2830.67,3976.66 2823.3,3969.3 2719.7,3969.3 2717,3972 2727.5,3982.5 2769.88,3982.5 2783.73,3996.35 2830.67,3996.35
1V8 on Bottom Layer "1V8_L08_P636" (solid, remove dead copper, pour order 636): 2808.44,4117 2808.44,4097.36 2799.66,4088.58 2763.46,4088.58 2750.52,4075.64 2750.52,4067.24 2753.1,4064.66 2830.67,4064.66 2830.67,4111.33 2825,4117
PVIN3V3 on Bottom Layer "PVIN3V3_L08_P712" (solid, remove dead copper, pour order 712): 33 vertices, not listed, extent 2400.86,1532.95 2545.28,2219.93
SW_B3 on Bottom Layer "SW_B3_L08_P705" (solid, remove dead copper, pour order 705): 2583.76,2085.6 2486.21,2085.6 2470,2101.81 2470,2125.81 2443.93,2151.88 2443.93,2204.4 2445.08,2205.56 2452.62,2205.56 2453.77,2204.4 2453.77,2168.04 2492,2129.81 2567.1,2129.81 2583.76,2113.16
PMIC_EN on Bottom Layer "PMIC_EN_L08_P649" (solid, remove dead copper, pour order 649): 2468.8,2204.47 2499.53,2204.47 2510,2194 2510,2173 2505,2168 2467,2168 2463.46,2171.54 2463.46,2203.24 2464.69,2204.47
1V8 on Bottom Layer "1V8_L08_P690" (solid, remove dead copper, pour order 690): 2848,2223 cw(c2848,2213) 2858,2213 2858,2165 cw(c2851,2165) 2851,2158 2754,2158 cw(c2754,2182) 2730,2182 2729.81,2230.64 2729.81,2273.95 2798.71,2273.95 2798.71,2230.64 ccw(c2806.35,2230.64) 2806.35,2223
PMICOUT_1V8 on Bottom Layer "PMICOUT_1V8_L08_P653" (solid, remove dead copper, pour order 653): 2248.29,1869.91 ccw(c2236.45,1881.75) 2253.2,1881.75 2253.2,1900 2253.2,1957.04 2250.67,1959.57 2218.44,1959.57 2216.2,1957.33 2216.2,1894.81 2216.2,1881 2216.2,1877.66 ccw(c2229.86,1877.66) 2220.2,1868 ccw(c2229.86,1877.66) 2229.86,1864 2233.19,1863.81 2234.68,1863.81 ccw(c2234.84,1881.59) 2247.29,1868.91
3V3_VIO on Bottom Layer "3V3_VIO_L08_P693" (solid, remove dead copper, pour order 693): 26 vertices, not listed, extent 2076,1754.54 2216,1989.25
NetC1_2 on Bottom Layer "NETC1_2_L08_P665" (solid, remove dead copper, pour order 665): 2532.75,4794.5 2532.75,4693.34 2524.95,4685.54 2429.14,4685.54 2421.19,4693.49 2421.19,4750.84 2464.85,4794.5
PMICOUT_1V2 on Bottom Layer "PMICOUT_1V2_L08_P708" (solid, remove dead copper, pour order 708): 19 vertices, not listed, extent 2508.95,1886.82 2872.45,2050.16
3V3 on Bottom Layer "3V3_L08_P667" (solid, remove dead copper, pour order 667): 1998,1808 1998,1770 2013.46,1754.54 2082.13,1754.54 2082.13,1823.43 2013.43,1823.43
AGND on Bottom Layer "AGND_L08_P668" (solid, remove dead copper, pour order 668): 21 vertices, not listed, extent 2346.48,2223.31 2472.48,2293.31
1V2_FILTERED on Bottom Layer "1V2_FILTERED_L08_P711" (solid, remove dead copper, pour order 711): 17 vertices, not listed, extent 2895.2,1881.8 3284.8,2016.73
VDDIO_ETH2 on Bottom Layer "VDDIO_ETH2_L08_P674" (solid, remove dead copper, pour order 674): 1318.9,2904.34 1342.52,2904.34 1342.52,2962.6 1351.6,2971.68 1351.6,3044.15 1345.88,3049.87 1326.99,3049.87 1322.07,3044.95 1322.07,3033.39 1318.9,3030.22 1318.9,2962.6
PMICOUT_1V0 on Bottom Layer "PMICOUT_1V0_L08_P676" (solid, remove dead copper, pour order 676): 1963.9,3228.7 1968.7,3233.5 1968.7,3260.07 1963.95,3264.92 1873.98,3264.92 1872.81,3263.76 1872.81,3229.87 1873.98,3228.7
PMICOUT_1V2 on Bottom Layer "PMICOUT_1V2_L08_P678" (solid, remove dead copper, pour order 678): 1872.81,3337.26 1873.98,3338.42 1978.1,3338.42 1989.86,3326.66 1989.86,3306.97 1985.1,3302.2 1873.98,3302.2 1872.81,3303.37 1872.81,3304.2
1V8_FILTERED on Bottom Layer "1V8_FILTERED_L08_P696" (solid, remove dead copper, pour order 696): 2992.83,2362.83 3102.9,2472.9 3102.9,2564.94 2882.15,2564.94 2878.39,2561.18 2874.83,2557.43 2874.83,2535.6 2797.18,2457.95 2757.81,2457.95 2757.81,2417.02 2729.81,2389.02 2729.81,2336.94 2798.71,2336.94 2824.6,2362.83
1V0_FILTERED on Bottom Layer "1V0_FILTERED_L08_P685" (solid, remove dead copper, pour order 685): 23 vertices, not listed, extent 1736.49,2290.76 2057.78,2562.47
PMIC_LDO_1V0 on Bottom Layer "PMIC_LDO_1V0_L08_P680" (solid, remove dead copper, pour order 680): 1872.82,3409.92 1873.4,3410.51 1873.4,3411.33 1889.55,3427.48 1982.73,3427.48 1988.25,3421.96 1988.25,3388.02 1975.93,3375.7 1873.98,3375.7 1872.82,3376.86 1872.82,3377.69
NetC24_2 on Bottom Layer "NETC24_2_L08_P683" (solid, remove dead copper, pour order 683): 1238.26,3372.91 1238.26,3324.74 1244.09,3318.9 1283.47,3318.9 1294.53,3329.96 1294.53,3372.91
REGOUT_3V3 on Bottom Layer "REGOUT_3V3_L08_P684" (solid, pour order 684): 1902,2061.62 1868.38,2061.62 1856.17,2073.84 1856.61,2074.28 1856.61,2109.2 1867.25,2119.84 1900.87,2119.84 1902,2118.71
REGOUT_3V3 on Bottom Layer "REGOUT_3V3_L08_P686" (solid, remove dead copper, pour order 686): 1890,495.81 1882.73,503.09 1882.73,548.54 1874.46,556.81 1863,556.81 1854,565.81 1854,599.81 1904.38,599.81 1929.54,574.65 1943.07,574.65 1943.07,513.38 1925.5,495.81
1V0 on Bottom Layer "1V0_L08_P692" (solid, remove dead copper, pour order 692): 1929.9,2360.85 1888.15,2360.85 1854,2395 1739,2395 1732,2388 1732,2296 1749,2279 1919.33,2279 1931.09,2290.76 1931.09,2359.66
PMICOUT_1V2 on Bottom Layer "PMICOUT_1V2_L08_P651" (solid, remove dead copper, pour order 651): 2183.09,1868.91 ccw(c2171.25,1880.75) 2188,1880.75 2188,1899 2188,1956.04 2185.47,1958.57 2153.24,1958.57 2151,1956.33 2151,1893.81 2151,1880 2151,1876.66 ccw(c2164.66,1876.66) 2155,1867 ccw(c2164.66,1876.66) 2164.66,1863 2167.99,1862.81 2169.48,1862.81 ccw(c2169.64,1880.59) 2182.09,1867.91
VBAT_INT on Bottom Layer "VBAT_INT_L08_P695" (solid, remove dead copper, pour order 695): 2862,915 2862,925.48 2881.56,945.03 3035.1,945.03 3052,928.13 3052,754.91 3049.09,752 2916,752 cw(c2916,806) 2862,806 2862,876
NetFB2_1 on Bottom Layer "NETFB2_1_L08_P661" (solid, remove dead copper, pour order 661): 1709,3381 1739.34,3411.34 1848.61,3411.34 1849.19,3410.75 1849.19,3229.87 1848.02,3228.7 1787,3228.7 1787,3282 1763,3306 1714.65,3306 1709,3311.78
PMICOUT_1V8 on Bottom Layer "PMICOUT_1V8_L08_P697" (solid, remove dead copper, pour order 697): 2805.51,2566.94 2805.51,2493.42 2791.09,2479 2749,2479 2734.19,2464.19 2734.19,2457.95 2734.19,2420.55 2678.61,2364.97 2630.29,2364.97 2630.29,2384.65 2607.76,2407.18 2607.76,2522.44 2607.76,2566.94
VDDIO_ETH2 on Bottom Layer "VDDIO_ETH2_L08_P717" (solid, remove dead copper, pour order 717): 18 vertices, not listed, extent 1548,2995.11 1716.54,3227.51
NetJ10_1 on Bottom Layer "Bottom Layer-NetJ10_1" (solid, remove dead copper, pour order 729): 133.34,4342.92 243.46,4342.92 295.09,4291.29 295.09,4229.02 208.81,4229.02 208.81,4288.22 179.15,4317.88 133.86,4317.88
NetC97_1 on Bottom Layer "Bottom Layer-NetC97_1" (solid, remove dead copper, pour order 736): 370.95,4224.8 405.68,4224.8 405.68,4281.04 370.97,4315.75 370.97,4352.47 352.96,4370.48 284.18,4370.48 284.18,4341.18 319.92,4305.43 319.92,4224.8
FTDI_VBUS on Bottom Layer "Bottom Layer-FTDI_VBUS 1" (solid, remove dead copper, pour order 738): 208.05,4209.29 295.09,4209.29 450.35,4209.29 450.35,4038.03 339.78,4038.03 339.78,4142.83 208.05,4142.83
FTDI_3V3 on Bottom Layer "Bottom Layer-FTDI_3V3 1" (solid, remove dead copper, pour order 739): 580.93,4199.45 580.93,4341.18 521.58,4341.18 521.58,4199.45
FTDI_3V3 on Bottom Layer "Bottom Layer-FTDI_3V3" (solid, remove dead copper, pour order 741): 1247.52,4672.69 1468.62,4672.69 1468.62,4570.69 1325.51,4570.69 1313.48,4582.73 1272.92,4582.73 1247.36,4608.29
VLDO_3V3 on Bottom Layer "Bottom Layer-VLDO_3V3" (solid, remove dead copper, pour order 742): 1614.4,4595.35 1602.59,4583.54 1602.59,4520.65 1600.64,4518.7 1551.93,4518.7 1550.02,4520.61 1550.02,4540.03 1530.63,4559.41 1491.9,4559.34 1492.23,4690.52 1614.4,4690.52
FTDI_VBUS on Bottom Layer "Bottom Layer-FTDI_VBUS" (solid, remove dead copper, pour order 745): 1579.85,4332.46 1567.35,4332.46 1556,4343.81 1556,4481.96 1579.47,4505.43 1607.52,4505.43 1608.28,4504.67 1608.28,4332.46
NetJ9_15 on Bottom Layer "Bottom Layer-NetJ9_15" (solid, remove dead copper, pour order 756): 366.88,2100.54 366.88,2202.15 351.78,2217.25 351.78,2275.46 382.29,2305.97 464.22,2305.97 464.22,2100.54
ERTH_GND on Bottom Layer "Bottom Layer-ERTH_GND" (solid, remove dead copper, pour order 757): 253.7,2228.6 351.78,2228.6 351.78,1975.88 252.91,1975.88
ERTH_GND on Bottom Layer "Bottom Layer-ERTH_GND 1" (solid, remove dead copper, pour order 759): 354.63,3081.36 405.78,3081.36 423.43,3099.01 423.43,3164.17 495.64,3164.22 495.64,3016.36 354.63,3016.36
NetJ9_16 on Bottom Layer "Bottom Layer-NetJ9_16" (solid, remove dead copper, pour order 761): 459.43,2999.34 459.43,2839.67 427.54,2807.77 374.98,2807.77 349.71,2833.05 349.71,2902.87 379.45,2932.61 379.45,2999.34
NetJ10_6 on Bottom Layer "Bottom Layer-NetJ10_6" (solid, remove dead copper, pour order 763): 192.3,4450.41 199.96,4458.07 199.96,4517.55 164.33,4553.18 -19.57,4553.18 -19.57,4151.18 189.34,4151.18 189.34,4307.69 179.15,4317.88 113.86,4317.88 104.25,4327.49 104.25,4449.7
FTDI_VCORE on Bottom Layer "Bottom Layer-FTDI_VCORE" (solid, remove dead copper, pour order 764): 1255.4,4125.81 1260.4,4130.81 1280.78,4130.81 1337.12,4074.47 1337.12,3977.12 1332,3972 1296.66,3972 1290.33,3978.33 1284.15,3984.5 1284.15,4017.91 1255.4,4046.65
GND on PWR1 "PWR2-GND" (solid, remove dead copper, pour order 766): 0,4921.25 3346.45,4921.25 3346.45,0 0,0
1V0 on PWR1 "PWR1-1V0_RF1" (solid, remove dead copper, pour order 750): 36 vertices, not listed, extent 1714.62,2272 2409,4061
1V2 on PWR1 "PWR1-1V2" (solid, remove dead copper, pour order 751): 46 vertices, not listed, extent 2444,2106.4 3316.3,4289
PVIN3V3 on PWR1 "PVIN3V3_L04_P749" (solid, remove dead copper, pour order 749): 26 vertices, not listed, extent 2110,1549 2547.24,2526
3V3 on PWR1 "3V3_L04_P631" (solid, remove dead copper, pour order 631): 2527.88,3604.3 2535.44,3611.86 2564.15,3611.86 2571,3605.02 2571,3562.82 2564.18,3556 2533.32,3556 2527.88,3561.45
FTDI_3V3 on PWR1 "PWR1-FTDI_3V3" (solid, remove dead copper, pour order 647): 513.61,4230.71 513.61,4373.89 700.38,4560.65 799.23,4560.65 921.37,4682.8 1392.36,4682.8 1446,4629.16 1446,4271 1423,4248 1357.32,4248 1210.25,4395.06 739.18,4395.06 608.35,4264.24 608.35,4230.71
3V3_VIO on PWR1 "3V3_VIO_L04_P664" (solid, remove dead copper, pour order 664): 1706,4104 1618,4016 1618,4005 1699,4005 1704,4010
AGND on PWR1 "AGND_L04_P748" (solid, remove dead copper, pour order 748): 21 vertices, not listed, extent 2346.48,2223.31 2472.48,2293.31
3V3_VIO on PWR1 "3V3_VIO_L04_P752" (solid, remove dead copper, pour order 752): 2225.81,1747.81 2234.92,1757 2234.92,1817.54 2221.97,1830.49 2179.8,1830.49 2164.06,1814.74 2164.06,1757.44 2173.8,1747.81
REGOUT_3V3 on PWR2 "REGOUT_3V3_L05_P772" (solid, remove dead copper, pour order 772): 1780,1642.4 1765.83,1628.24 1734.76,1628.24 1717,1646 1767,1696 1780,1696
GND on PWR2 "PWR2-GND" (solid, remove dead copper, pour order 770): 0,4921.25 3346.45,4921.25 3346.45,0 0,0
REGOUT_3V3 on PWR2 "PWR1-REGOUT_3V3" (solid, remove dead copper, pour order 760): 17 vertices, not listed, extent 1087.26,285.81 1978,1133
REGOUT_3V3 on PWR2 "PWR1-REGOUT_3V3" (solid, remove dead copper, pour order 754): 2911.41,1411.41 2920,1420 2938.67,1401.33 2938.67,1273.48 2909.19,1244 2740.57,1244 2700.13,1284.43 2700.13,1369.02 2742.52,1411.41
REGOUT_3V3 on PWR2 "REGOUT_3V3_L05_P630" (solid, remove dead copper, pour order 630): 2048,2056 2069,2056 2080,2045 2080,2009 2074.08,2003.08 2044.92,2003.08 2040,2008 2040,2048
PMICOUT_1V8 on PWR2 "PMICOUT_1V8_L05_P730" (solid, remove dead copper, pour order 730): 2215.27,1899.77 2215.27,1865.73 2229.74,1851.26 2245.26,1851.26 2266.5,1872.5 2266.5,1900 2258.5,1908 2223.5,1908
VDDIO_ETH2 on PWR2 "PWR2-VDDIO_ETH2" (solid, remove dead copper, pour order 753): 22 vertices, not listed, extent 967.94,2884.22 1767.86,3449.81
1V8 on PWR2 "PWR2-1V8" (solid, remove dead copper, pour order 710): 64 vertices, not listed, extent 1913,2154 3205,4324.51
PMICOUT_1V2 on PWR2 "PMICOUT_1V2_L05_P723" (solid, remove dead copper, pour order 723): 2139,1878 2139,1930.72 2179.7,1971.42 2187,1964.12 2187,1885 2165.67,1863.67 2153.33,1863.67
PMIC_LDO_1V0 on PWR2 "PMIC_LDO_1V0_L05_P714" (solid, remove dead copper, pour order 714): 2394,2130 2394,2096 2386,2088 2369,2088 2364.81,2092.19 2364.81,2128.81 2373,2137 2387,2137
PMICOUT_1V2 on PWR2 "PMICOUT_1V2_L05_P728" (solid, remove dead copper, pour order 728): 2605,2049 2605,2010 2677.6,1937.4 2801.18,1937.4 2810,1946.22 2810,2006 2794,2022 2694,2022 2667,2049
AGND on PWR2 "AGND_L05_P724" (solid, remove dead copper, pour order 724): 21 vertices, not listed, extent 2346.48,2223.31 2472.48,2293.31
PMICOUT_1V8 on PWR2 "PMICOUT_1V8_L05_P731" (solid, remove dead copper, pour order 731): 2655.26,2527.68 2655.26,2449.32 2667.45,2437.13 2722.19,2437.13 2737.87,2452.81 2737.87,2523.8 2722.19,2539.49 2667.07,2539.49
VBAT_INT on PWR2 "VBAT_INT_L05_P732" (solid, remove dead copper, pour order 732): 2862,967 2862,870.28 2933.07,799.21 2972.44,799.21 3031.5,858.27 3031.5,929.13 2978.63,982 2877,982
VBAT_INT on PWR2 "VBAT_INT_L05_P733" (solid, remove dead copper, pour order 733): 535,3217 558.19,3193.81 616,3193.81 632,3209.81 632,3325.81 617,3340.81 544,3340.81 535,3331.81
GND on GND1 "GND1-GND" (solid, remove dead copper, pour order 663): 0,4921.25 3346.45,4921.25 3346.45,0 0,0
ERTH_GND on GND1 "ERTH_GND_L02_P656" (solid, remove dead copper, pour order 656): 249.86,2975.14 275.14,2975.14 290,2990 289.86,3015.14 374.2,3099.48 523.85,3099.49 523.85,2859.92 482.54,2818.61 482.54,2253.34 362.83,2133.63 225.68,2133.63 144.93,2214.38 0,2214.38 0,2906.57 181.29,2906.57
AGND on GND1 "AGND_L02_P646" (solid, pour order 646): 17 vertices, not listed, extent 2346.38,2225.45 2471.38,2292.38
no net on Top Solder "NONET_L-01_P-001" (solid): 21 vertices, not listed, extent 2232.24,3647.86 2727.51,4138.08
no net on Top Solder (solid): 1601.73,4452.2 1689.62,4452.2 1689.62,4570.74 1601.73,4570.74

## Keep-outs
GND2:
  circle w1: c2674.75,3847.07 r6.86
  circle w1: c2700.34,3847.07 r6.86
  circle w1: c2700.34,3821.48 r6.86
  circle w1: c2674.75,3821.48 r6.86
  circle w1: c2700.34,3898.25 r6.86
  circle w1: c2674.75,3898.25 r6.86
  circle w1: c2700.34,3923.84 r6.86
  circle w1: c2674.75,3923.84 r6.86
  circle w1: c2700.34,3949.43 r6.86
  circle w1: c2674.75,3949.43 r6.86
Keep-Out Layer:
  text ".Layer_Name" at 931.33,-846.68 h60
